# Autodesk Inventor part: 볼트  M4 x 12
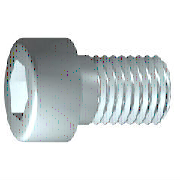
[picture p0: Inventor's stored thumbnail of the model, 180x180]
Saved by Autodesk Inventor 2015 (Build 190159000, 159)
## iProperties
IsCustomPart: 1
Created: 2012-02
Part Number: 볼트  M4 x 12
Material: 강철, 연강
Description: 6각 소켓 머리 캡 나사
Document SubType Name: Modeling
Standard: ISO 4762
Designer: mdu-01
Standard Revision: Fourth edition 2004-03-01
Standards Organization: ISO
Language: ko-KR
Size Designation: M4 x 12
Categories: <MemberInstance><Categories><Category DisplayName="조임쇠" InternalName="e4da775c-781d-43d5-af7c-5136215cf5a6" Mnemonic="FSTN"><Category DisplayName="볼트" InternalN
Density: 7.75 g/cm^3
Appearance: 강철
Author: mdu-01
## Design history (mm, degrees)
sketch "스케치1"
  geometry: L1 (-1, 0)-(12, 0); L2 (12, 0)-(12, 2); L3 (12, 2)-(1.75, 2); L4 (1.75, 2)-(1.32, 2); L5 (1.32, 2)-(0, 2); L6 (0, 2)-(0, 3.5); L7 (0, 3.5)-(-4, 3.5); L8 (-4, 3.5)-(-4, 1.732); L9 (-4, 1.732)-(-2, 1.732); L10 (-2, 1.732)-(-1, 0); L11 (-7.2, 0)-(15.2, 0) reference; L12 (0, -0.7)-(0, 4.2) reference; L13 (1.75, 2)-(0, 2)
  constraints: 22 end point, 6 parallel, 2 collinear, 2 perpendicular, 1 horizontal, 1 point on line
  dimensions: "d1" = 10.25 distance from line of L3.end L2 (= GEL); "d2" = 0.42952 distance of L4.end L3.end (computed from GAL); "d3" = 4 distance between parallel lines of L8 L6 (= KOH); "d4" = 2 distance of L8.end L9.end (= INTI); "d5" = 60 deg angle of L10 L1; "d6" = 4 diameter of L3 L1 (= GD); "d7" = 4 diameter of L5 L1 (= BDM); "d8" = 3.4641 diameter of L9 L1 (= 1.1547 x SW); "d9" = 7 diameter of L7 L1 (= KOD); "d26" = 12 distance between parallel lines of L12 L2 (= NLG)
revolve "본체" sketch "스케치1" stored, may be unused: angle "d10" = 90 deg
sketch "스케치2"
  geometry: L1 (0, -4.9)-(0, 4.9) reference; L2 (-4.9, 0)-(4.9, 0) reference; L3 (1.732, 0)-(0.866, -1.5); L4 (0.866, -1.5)-(-0.866, -1.5); L5 (-0.866, -1.5)-(-1.732, 0); L6 (-1.732, 0)-(-0.866, 1.5); L7 (-0.866, 1.5)-(0.866, 1.5); L8 (0.866, 1.5)-(1.732, 0); 2 further points
  constraints: 12 end point, 1 coincident, 1 horizontal alignment, 1 point on line, 12 other
extrude "슬롯" join sketch "스케치2" stored distance "d11" = 10; taper "d12" = 0 deg
workplane "Work Plane1"
fillet "Fillet2" dims "d30" = 0.1 (= R)
body "Solid1"
fillet "모깎기1" dims "d17" = 0.4 (= RR)
feature "스레드" dims "d13" = 10.25 (= GEL), "d14" = 0
chamfer "모따기1" distance "d15" = 0.42941 (= -0.5 x SPD + 0.5 x GD); stored, may be unused: second distance "d16" = 0.42941 (= GUL), angle "d27" = 45 deg
other parameters: "GD" = 4 [user parameter; used in 2 equation terms], "NLG" = 12 [user parameter; used in 1 equation term], "GEL" = 10.25 [user parameter; used in 2 equation terms], "KOD" = 7 [user parameter; used in 1 equation term], "KOH" = 4 [user parameter; used in 1 equation term], "INTI" = 2 [user parameter; used in 1 equation term], "GAL" = 0.42941 (= 0.61345 x PTC) [user parameter; used in 1 equation term], "GUL" = 0.42941 (= 0.61345 x PTC) [user parameter; used in 1 equation term], "BDM" = 4 (= NND) [user parameter; used in 1 equation term], "SW" = 3 [user parameter; used in 2 equation terms], "RR" = 0.4 [user parameter; used in 1 equation term], "SPD" = 3.14117 (= NND - 1.2269 x PTC) [user parameter; used in 1 equation term], "d19" = 0, "d28" = 0, "d29" = 0, "R" = 0.1 [user parameter; used in 1 equation term], "TOA" = 30 deg [user parameter], "GD1" = 3.14117 (= THREADDIA - 1.2269 x PTC) [user parameter], "THREADDIA" = 4 [user parameter; used in 1 equation term], "FAWI" = 45 deg [user parameter], "TPU" = 14.28571 (computed from PTC) [user parameter], "PTC" = 0.7 [user parameter; used in 5 equation terms], "NND" = 4 [user parameter; used in 2 equation terms], "E0" = 3.465 (= 1.155 x SW) [user parameter]
